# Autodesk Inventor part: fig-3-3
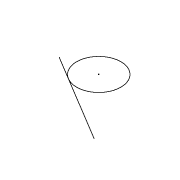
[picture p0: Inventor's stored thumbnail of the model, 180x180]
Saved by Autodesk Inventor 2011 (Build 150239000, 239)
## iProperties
Created: 2009-11
Part Number: fig-3-3
Document SubType Name: Modeling
Designer: Sham
Density: 1 g/cm^3
Author: Sham
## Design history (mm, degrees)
sketch "Sketch1"
  geometry: L1 (-21, -10.296)-(20, -35); C1 r 10.296 at (-4.831, -8.018)
  constraints: 2 end point, 1 centre point, 1 tangent, 1 other
